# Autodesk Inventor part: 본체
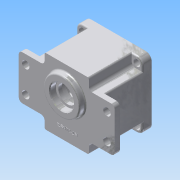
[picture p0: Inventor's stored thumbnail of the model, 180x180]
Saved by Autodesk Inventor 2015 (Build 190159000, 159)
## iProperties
Created: 2015-06
Part Number: 본체
Material: 알루미늄 6061
Document SubType Name: Modeling
Designer: AMC
Density: 2.7 g/cm^3
Appearance: 알루미늄 - 평지
Mass: 682.745 g
Surface Area: 675.046 cm^2
Volume: 252.868 cm^3
Author: AMC
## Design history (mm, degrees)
sketch "스케치1"
  geometry: L1 (0, 0)-(90, 0); L2 (90, 0)-(90, 90); L3 (90, 90)-(0, 90); L4 (0, 90)-(0, 0)
  constraints: 8 end point, 2 parallel, 1 horizontal, 1 perpendicular
  dimensions: "d0" = 90 distance of L2.end L3.end; "d1" = 90 distance of L1.end L2.end
extrude "돌출1" new body sketch "스케치1" distance "d2" = 12; taper "d3" = 0 deg
sketch "스케치2"
  geometry: L1 (75, 75)-(15, 75); L2 (15, 75)-(15, 15); L3 (15, 15)-(75, 15); L4 (75, 15)-(75, 75); L5 (90, 90)-(0, 90) reference; L6 (90, 0)-(90, 90) reference; 5 further points
  constraints: 8 end point, 4 midpoint, 2 parallel, 1 horizontal, 1 horizontal alignment, 1 perpendicular, 1 vertical alignment
  dimensions: "d4" = 60 distance of L3.end L1.start; "d5" = 60 distance of L1.start L1.end
extrude "돌출2" join sketch "스케치2" distance "d6" = 58; taper "d7" = 0 deg
sketch "스케치3"
  geometry: L1 (75, 75)-(75, 15) reference; L2 (75, 15)-(15, 15) reference; L3 (15, 15)-(15, 75) reference; L4 (15, 75)-(75, 75) reference; L5 (75, 110)-(15, 110); L6 (15, 110)-(15, -20); L7 (15, -20)-(75, -20); L8 (75, -20)-(75, 110); L9 (90, 90)-(0, 90) reference; L10 (90, 0)-(90, 90) reference; 5 further points
  constraints: 8 end point, 4 midpoint, 2 parallel, 1 horizontal, 1 horizontal alignment, 1 perpendicular, 1 vertical alignment
  dimensions: "d8" = 130 distance of L7.end L5.start; "d9" = 60 distance of L5.start L5.end
extrude "돌출3" join sketch "스케치3" distance "d10" = 7; taper "d11" = 0 deg
fillet "모깎기1" dims "d12" = 5
fillet "모깎기2" dims "d13" = 8
fillet "모깎기3" dims "d14" = 5
sketch "스케치4"
  geometry: L1 (15, 20)-(15, 70) reference; L2 (20, 75)-(70, 75) reference; L3 (75, 70)-(75, 20) reference; L4 (70, 15)-(20, 15) reference; L5 (8, 90)-(82, 90) reference; L6 (90, 82)-(90, 8) reference; L7 (82, 0)-(8, 0) reference; L8 (0, 8)-(0, 82) reference; C1 r 4.5 at (82, 82); C2 r 4.5 at (82, 8); C3 r 4.5 at (8, 8); C4 r 4.5 at (8, 82); A1 r 5 centre (20, 20) between (15, 20) and (20, 15) reference; A2 r 5 centre (20, 70) between (20, 75) and (15, 70) reference; A3 r 5 centre (70, 70) between (75, 70) and (70, 75) reference; A4 r 5 centre (70, 20) between (70, 15) and (75, 20) reference; A5 r 8 centre (8, 82) between (8, 90) and (0, 82) reference; A6 r 8 centre (82, 82) between (90, 82) and (82, 90) reference; A7 r 8 centre (82, 8) between (82, 0) and (90, 8) reference; A8 r 8 centre (8, 8) between (0, 8) and (8, 0) reference; 1 further point
  constraints: 4 centre point, 4 coincident
  dimensions: "d15" = 9 diameter of C1; "d16" = 9 diameter of C2; "d17" = 9 diameter of C3; "d18" = 9 diameter of C4
extrude "돌출4" cut sketch "스케치4" distance "d19" = 7; taper "d20" = 0 deg
sketch "스케치5"
  geometry: L1 (75, 105)-(75, -15) reference; L2 (70, -20)-(20, -20) reference; L3 (15, -15)-(15, 105) reference; L4 (20, 110)-(70, 110) reference; L5 (90, 75)-(0, 75); L6 (0, 75)-(0, 15); L7 (0, 15)-(90, 15); L8 (90, 15)-(90, 75); L9 (90, 8)-(90, 82) reference; A1 r 5 centre (70, -15) between (70, -20) and (75, -15) reference; A2 r 5 centre (20, -15) between (15, -15) and (20, -20) reference; A3 r 5 centre (20, 105) between (20, 110) and (15, 105) reference; A4 r 5 centre (70, 105) between (75, 105) and (70, 110) reference; 5 further points
  constraints: 8 end point, 4 midpoint, 2 parallel, 1 coincident, 1 horizontal, 1 perpendicular, 1 vertical alignment
  dimensions: "d21" = 60 distance of L7.end L5.start; "d22" = 90 distance of L6.end L7.end
extrude "돌출5" join sketch "스케치5" stored distance "d23" = 7; taper "d24" = 0 deg
sketch "스케치6"
  geometry: L1 (0, 8)-(0, 15) reference; L2 (0, 15)-(0, 75) reference; L3 (0, 75)-(0, 82) reference; L4 (8, 90)-(82, 90) reference; L5 (90, 82)-(90, 75) reference; L6 (90, 75)-(90, 15) reference; L7 (90, 15)-(90, 8) reference; L8 (82, 0)-(8, 0) reference; L9 (90, 15)-(0, 15) reference; L10 (0, 75)-(90, 75) reference; L11 (75, 90)-(15, 90); L12 (15, 90)-(15, 0); L13 (15, 0)-(75, 0); L14 (75, 0)-(75, 90); C1 r 4.5 at (8, 8) reference; C2 r 4.5 at (82, 82) reference; C3 r 4.5 at (82, 8) reference; C4 r 4.5 at (8, 82) reference; A1 r 8 centre (8, 82) between (8, 90) and (0, 82) reference; A2 r 8 centre (82, 82) between (90, 82) and (82, 90) reference; A3 r 8 centre (82, 8) between (82, 0) and (90, 8) reference; A4 r 8 centre (8, 8) between (0, 8) and (8, 0) reference; 5 further points
  constraints: 8 end point, 4 midpoint, 2 parallel, 1 coincident, 1 horizontal, 1 horizontal alignment, 1 perpendicular
  dimensions: "d25" = 90 distance of L13.end L11.start; "d26" = 60 distance between parallel lines of L12 L14
extrude "돌출6" join sketch "스케치6" stored distance "d27" = 7; taper "d28" = 0 deg
fillet "모깎기4" dims "d29" = 5
sketch "스케치7"
  geometry: L1 (75, 10)-(75, -15) reference; L2 (70, -20)-(20, -20) reference; L3 (15, -15)-(15, 10) reference; L4 (10, 15)-(0, 15) reference; L5 (0, 15)-(0, 75) reference; L6 (0, 75)-(10, 75) reference; L7 (15, 80)-(15, 105) reference; L8 (20, 110)-(70, 110) reference; L9 (75, 105)-(75, 80) reference; L10 (80, 75)-(90, 75) reference; L11 (90, 75)-(90, 15) reference; L12 (90, 15)-(80, 15) reference; C1 r 5.072 at (62.5, 100.571); C2 r 5.147 at (62.5, -9.429); A1 r 5 centre (80, 10) between (80, 15) and (75, 10) reference; A2 r 5 centre (70, -15) between (70, -20) and (75, -15) reference; A3 r 5 centre (20, -15) between (15, -15) and (20, -20) reference; A4 r 5 centre (10, 10) between (15, 10) and (10, 15) reference; A5 r 5 centre (10, 80) between (10, 75) and (15, 80) reference; A6 r 5 centre (20, 105) between (20, 110) and (15, 105) reference; A7 r 5 centre (70, 105) between (75, 105) and (70, 110) reference; A8 r 5 centre (80, 80) between (75, 80) and (80, 75) reference; 1 further point
  constraints: 2 centre point
  dimensions: "d30" = 110 distance of C2.centre C1.centre; "d31" = 12.5 distance from line of C1.centre L9
extrude "돌출7" cut sketch "스케치7" distance "d32" = 7; taper "d33" = 0 deg
node "작업 평면1"
fillet "모깎기5" dims "d34" = 2
node "작업 평면2"
sketch "스케치9"
  geometry: L1 (-8, 70)-(82, 70) reference; L2 (82, 70)-(82, 0) reference; L3 (82, 0)-(-8, 0) reference; L4 (-8, 0)-(-8, 70) reference; L5 (37, 88.411)-(37, -11); L6 (77, 0)-(77, 9); L7 (77, 9)-(76, 9); L8 (76, 9)-(76, 61); L9 (76, 61)-(37, 61); L10 (77, 0)-(37, 0); L11 (37, 61)-(37, 0)
  constraints: 14 end point, 3 vertical, 2 collinear, 2 perpendicular, 1 midpoint, 1 point on line
  dimensions: "d39" = 9 distance of L6.start L6.end; "d40" = 1 distance of L6.end L7.end; "d42" = 52 distance of L7.end L8.end
revolve "회전1" sketch "스케치9" stored, may be unused: angle "d46" = 90 deg
sketch "스케치11"
  geometry: L1 (-30, 35)-(-30, 43) reference; L2 (-28, 45)-(28, 45) reference; L3 (30, 43)-(30, 35) reference; L4 (35, 30)-(43, 30) reference; L5 (45, 28)-(45, -28) reference; L6 (43, -30)-(35, -30) reference; L7 (30, -35)-(30, -43) reference; L8 (28, -45)-(-28, -45) reference; L9 (-30, -43)-(-30, -35) reference; L10 (-35, -30)-(-43, -30) reference; L11 (-45, -28)-(-45, 28) reference; L12 (-43, 30)-(-35, 30) reference; C1 r 39 at (0, 0) reference; C2 r 20.5 at (-11, 0); C3 r 14 at (20, 0); A1 r 5 centre (-35, 35) between (-35, 30) and (-30, 35) reference; A2 r 2 centre (-28, 43) between (-28, 45) and (-30, 43) reference; A3 r 2 centre (28, 43) between (30, 43) and (28, 45) reference; A4 r 5 centre (35, 35) between (30, 35) and (35, 30) reference; A5 r 2 centre (43, 28) between (45, 28) and (43, 30) reference; A6 r 2 centre (43, -28) between (43, -30) and (45, -28) reference; A7 r 5 centre (35, -35) between (35, -30) and (30, -35) reference; A8 r 2 centre (28, -43) between (28, -45) and (30, -43) reference; A9 r 2 centre (-28, -43) between (-30, -43) and (-28, -45) reference; A10 r 5 centre (-35, -35) between (-30, -35) and (-35, -30) reference; A11 r 2 centre (-43, -28) between (-45, -28) and (-43, -30) reference; A12 r 2 centre (-43, 28) between (-43, 30) and (-45, 28) reference; 1 further point
  constraints: 2 centre point
  dimensions: "d54" = 41 diameter of C2; "d55" = 11 distance of C1.centre C2.centre; "d56" = 28 diameter of C3; "d57" = 31 distance of C3.centre C2.centre
extrude "돌출9" join sketch "스케치11" distance "d58" = 7; taper "d59" = 0 deg
sketch "스케치12"
  geometry: L1 (-30, 35)-(-30, 43) reference; L2 (-28, 45)-(28, 45) reference; L3 (30, 43)-(30, 35) reference; L4 (35, 30)-(43, 30) reference; L5 (45, 28)-(45, -28) reference; L6 (43, -30)-(35, -30) reference; L7 (30, -35)-(30, -43) reference; L8 (28, -45)-(-28, -45) reference; L9 (-30, -43)-(-30, -35) reference; L10 (-35, -30)-(-43, -30) reference; L11 (-45, -28)-(-45, 28) reference; L12 (-43, 30)-(-35, 30) reference; C1 r 39 at (0, 0) reference; C2 r 17.5 at (-11, 0); A1 r 20.5 centre (-11, 0) between (6.5, 10.677) and (6.5, -10.677) reference; A2 r 12.5 centre (0, 0) between (9.006, 8.668) and (6.5, 10.677) reference; A3 r 14 centre (20, 0) between (9.006, -8.668) and (9.006, 8.668) reference; A4 r 12.5 centre (0, 0) between (6.5, -10.677) and (9.006, -8.668) reference; A5 r 5 centre (-35, 35) between (-35, 30) and (-30, 35) reference; A6 r 2 centre (-28, 43) between (-28, 45) and (-30, 43) reference; A7 r 2 centre (28, 43) between (30, 43) and (28, 45) reference; A8 r 5 centre (35, 35) between (30, 35) and (35, 30) reference; A9 r 2 centre (43, 28) between (45, 28) and (43, 30) reference; A10 r 2 centre (43, -28) between (43, -30) and (45, -28) reference; A11 r 5 centre (35, -35) between (35, -30) and (30, -35) reference; A12 r 2 centre (28, -43) between (28, -45) and (30, -43) reference; A13 r 2 centre (-28, -43) between (-30, -43) and (-28, -45) reference; A14 r 5 centre (-35, -35) between (-30, -35) and (-35, -30) reference; A15 r 2 centre (-43, -28) between (-45, -28) and (-43, -30) reference; A16 r 2 centre (-43, 28) between (-43, 30) and (-45, 28) reference; 1 further point
  constraints: 1 centre point, 1 coincident
  dimensions: "d60" = 35 diameter of C2
extrude "돌출10" cut sketch "스케치12" distance "d61" = 10; taper "d62" = 0 deg
node "작업 평면3"
sketch "스케치13"
  geometry: L1 (90, 17)-(90, 73) reference; L2 (20, 110)-(70, 110) reference; L3 (45, 110)-(45, -25.853); C1 r 25 at (56, 45); 2 further points
  constraints: 2 end point, 2 midpoint, 1 centre point, 1 horizontal alignment, 1 vertical
  dimensions: "d63" = 50 diameter of C1; "d65" = 11 distance from line of L3 C1.centre
extrude "돌출11" join sketch "스케치13" distance "d66" = 7; taper "d67" = 0 deg
hole "구멍2" diameter "d70" = 25; stored, may be unused: countersink angle "d74" = 90 deg, drill point angle "d76" = 118 deg; dims "d68" = 10, "d69" = 10, "d71" = 6, "d72" = 32, "d73" = 8, "d75" = 8
sketch "스케치14"
  geometry: L1 (-30, 35)-(-30, 43) reference; L2 (-28, 45)-(28, 45) reference; L3 (30, 43)-(30, 35) reference; L4 (35, 30)-(43, 30) reference; L5 (45, 28)-(45, -28) reference; L6 (43, -30)-(35, -30) reference; L7 (30, -35)-(30, -43) reference; L8 (28, -45)-(-28, -45) reference; L9 (-30, -43)-(-30, -35) reference; L10 (-35, -30)-(-43, -30) reference; L11 (-45, -28)-(-45, 28) reference; L12 (-43, 30)-(-35, 30) reference; C1 r 12.5 at (-11, 0) reference; C2 r 39 at (0, 0) reference; C3 r 20.5 at (-11, 0); C4 r 14 at (20, 0); A1 r 5 centre (-35, 35) between (-35, 30) and (-30, 35) reference; A2 r 2 centre (-28, 43) between (-28, 45) and (-30, 43) reference; A3 r 2 centre (28, 43) between (30, 43) and (28, 45) reference; A4 r 5 centre (35, 35) between (30, 35) and (35, 30) reference; A5 r 2 centre (43, 28) between (45, 28) and (43, 30) reference; A6 r 2 centre (43, -28) between (43, -30) and (45, -28) reference; A7 r 5 centre (35, -35) between (35, -30) and (30, -35) reference; A8 r 2 centre (28, -43) between (28, -45) and (30, -43) reference; A9 r 2 centre (-28, -43) between (-30, -43) and (-28, -45) reference; A10 r 5 centre (-35, -35) between (-30, -35) and (-35, -30) reference; A11 r 2 centre (-43, -28) between (-45, -28) and (-43, -30) reference; A12 r 2 centre (-43, 28) between (-43, 30) and (-45, 28) reference; 1 further point
  constraints: 2 centre point, 1 coincident
  dimensions: "d77" = 41 diameter of C3; "d78" = 31 distance of C4.centre C1.centre; "d79" = 28 diameter of C4
extrude "돌출12" join sketch "스케치14" distance "d80" = 7; taper "d81" = 0 deg
sketch "스케치15"
  geometry: L1 (-30, 35)-(-30, 43) reference; L2 (-28, 45)-(28, 45) reference; L3 (30, 43)-(30, 35) reference; L4 (35, 30)-(43, 30) reference; L5 (45, 28)-(45, -28) reference; L6 (43, -30)-(35, -30) reference; L7 (30, -35)-(30, -43) reference; L8 (28, -45)-(-28, -45) reference; L9 (-30, -43)-(-30, -35) reference; L10 (-35, -30)-(-43, -30) reference; L11 (-45, -28)-(-45, 28) reference; L12 (-43, 30)-(-35, 30) reference; C1 r 12.5 at (-11, 0) reference; C2 r 39 at (0, 0) reference; C3 r 17.5 at (-11, 0); A1 r 20.5 centre (-11, 0) between (8.117, 7.402) and (8.117, -7.402) reference; A2 r 14 centre (20, 0) between (8.117, -7.402) and (8.117, 7.402) reference; A3 r 5 centre (-35, 35) between (-35, 30) and (-30, 35) reference; A4 r 2 centre (-28, 43) between (-28, 45) and (-30, 43) reference; A5 r 2 centre (28, 43) between (30, 43) and (28, 45) reference; A6 r 5 centre (35, 35) between (30, 35) and (35, 30) reference; A7 r 2 centre (43, 28) between (45, 28) and (43, 30) reference; A8 r 2 centre (43, -28) between (43, -30) and (45, -28) reference; A9 r 5 centre (35, -35) between (35, -30) and (30, -35) reference; A10 r 2 centre (28, -43) between (28, -45) and (30, -43) reference; A11 r 2 centre (-28, -43) between (-30, -43) and (-28, -45) reference; A12 r 5 centre (-35, -35) between (-30, -35) and (-35, -30) reference; A13 r 2 centre (-43, -28) between (-45, -28) and (-43, -30) reference; A14 r 2 centre (-43, 28) between (-43, 30) and (-45, 28) reference; 1 further point
  constraints: 1 centre point, 1 coincident
  dimensions: "d82" = 35 diameter of C3
extrude "돌출13" cut sketch "스케치15" distance "d83" = 10; taper "d84" = 0 deg
sketch "스케치16"
  geometry: L1 (-30, 35)-(-30, 43) reference; L2 (-28, 45)-(28, 45) reference; L3 (30, 43)-(30, 35) reference; L4 (35, 30)-(43, 30) reference; L5 (45, 28)-(45, -28) reference; L6 (43, -30)-(35, -30) reference; L7 (30, -35)-(30, -43) reference; L8 (28, -45)-(-28, -45) reference; L9 (-30, -43)-(-30, -35) reference; L10 (-35, -30)-(-43, -30) reference; L11 (-45, -28)-(-45, 28) reference; L12 (-43, 30)-(-35, 30) reference; C1 r 17.5 at (-11, 0) reference; C2 r 39 at (0, 0) reference; C3 r 11 at (20, 0); A1 r 20.5 centre (-11, 0) between (8.117, 7.402) and (8.117, -7.402) reference; A2 r 14 centre (20, 0) between (8.117, -7.402) and (8.117, 7.402) reference; A3 r 5 centre (-35, 35) between (-35, 30) and (-30, 35) reference; A4 r 2 centre (-28, 43) between (-28, 45) and (-30, 43) reference; A5 r 2 centre (28, 43) between (30, 43) and (28, 45) reference; A6 r 5 centre (35, 35) between (30, 35) and (35, 30) reference; A7 r 2 centre (43, 28) between (45, 28) and (43, 30) reference; A8 r 2 centre (43, -28) between (43, -30) and (45, -28) reference; A9 r 5 centre (35, -35) between (35, -30) and (30, -35) reference; A10 r 2 centre (28, -43) between (28, -45) and (30, -43) reference; A11 r 2 centre (-28, -43) between (-30, -43) and (-28, -45) reference; A12 r 5 centre (-35, -35) between (-30, -35) and (-35, -30) reference; A13 r 2 centre (-43, -28) between (-45, -28) and (-43, -30) reference; A14 r 2 centre (-43, 28) between (-43, 30) and (-45, 28) reference; 1 further point
  constraints: 1 centre point, 1 coincident
  dimensions: "d85" = 22 diameter of C3
extrude "돌출14" cut sketch "스케치16" distance "d86" = 7; taper "d87" = 0 deg
sketch "스케치17"
  geometry: L1 (-50, 35)-(-50, 43) reference; L2 (-48, 45)-(8, 45) reference; L3 (10, 43)-(10, 35) reference; L4 (15, 30)-(23, 30) reference; L5 (25, 28)-(25, -28) reference; L6 (23, -30)-(15, -30) reference; L7 (10, -35)-(10, -43) reference; L8 (8, -45)-(-48, -45) reference; L9 (-50, -43)-(-50, -35) reference; L10 (-55, -30)-(-63, -30) reference; L11 (-65, -28)-(-65, 28) reference; L12 (-63, 30)-(-55, 30) reference; C1 r 11 at (0, 0) reference; C2 r 17.5 at (-31, 0) reference; C3 r 39 at (-20, 0) reference; C4 r 9.5 at (0, 0); A1 r 20.5 centre (-31, 0) between (-11.883, 7.402) and (-11.883, -7.402) reference; A2 r 14 centre (0, 0) between (-11.883, -7.402) and (-11.883, 7.402) reference; A3 r 5 centre (-55, 35) between (-55, 30) and (-50, 35) reference; A4 r 2 centre (-48, 43) between (-48, 45) and (-50, 43) reference; A5 r 2 centre (8, 43) between (10, 43) and (8, 45) reference; A6 r 5 centre (15, 35) between (10, 35) and (15, 30) reference; A7 r 2 centre (23, 28) between (25, 28) and (23, 30) reference; A8 r 2 centre (23, -28) between (23, -30) and (25, -28) reference; A9 r 5 centre (15, -35) between (15, -30) and (10, -35) reference; A10 r 2 centre (8, -43) between (8, -45) and (10, -43) reference; A11 r 2 centre (-48, -43) between (-50, -43) and (-48, -45) reference; A12 r 5 centre (-55, -35) between (-50, -35) and (-55, -30) reference; A13 r 2 centre (-63, -28) between (-65, -28) and (-63, -30) reference; A14 r 2 centre (-63, 28) between (-63, 30) and (-65, 28) reference; 1 further point
  constraints: 1 centre point, 1 coincident
  dimensions: "d88" = 19 diameter of C4
extrude "돌출15" cut sketch "스케치17" distance "d89" = 1; taper "d90" = 0 deg
sketch "스케치18" dims "d91" = 70
  geometry: L1 (-30, 35)-(-30, 43) reference; L2 (-28, 45)-(28, 45) reference; L3 (30, 43)-(30, 35) reference; L4 (35, 30)-(43, 30) reference; L5 (45, 28)-(45, -28) reference; L6 (43, -30)-(35, -30) reference; L7 (30, -35)-(30, -43) reference; L8 (28, -45)-(-28, -45) reference; L9 (-30, -43)-(-30, -35) reference; L10 (-35, -30)-(-43, -30) reference; L11 (-45, -28)-(-45, 28) reference; L12 (-43, 30)-(-35, 30) reference; L13 (0, 0)-(38.536, -38.536); L14 (0, 0)-(54.497, 0); L15 (26.331, -21.075)-(35.701, -25.112); L16 (23.543, -36.581)-(20.865, -25.705); L17 (19.284, -19.284)-(19.237, -19.093); C1 r 9.5 at (20, 0) reference; C2 r 11 at (20, 0) reference; C3 r 17.5 at (-11, 0) reference; C4 r 39 at (0, 0) reference; A1 r 20.5 centre (-11, 0) between (8.117, 7.402) and (8.117, -7.402) reference; A2 r 14 centre (20, 0) between (8.117, -7.402) and (8.117, 7.402) reference; A3 r 5 centre (-35, 35) between (-35, 30) and (-30, 35) reference; A4 r 2 centre (-28, 43) between (-28, 45) and (-30, 43) reference; A5 r 2 centre (28, 43) between (30, 43) and (28, 45) reference; A6 r 5 centre (35, 35) between (30, 35) and (35, 30) reference; A7 r 2 centre (43, 28) between (45, 28) and (43, 30) reference; A8 r 2 centre (43, -28) between (43, -30) and (45, -28) reference; A9 r 5 centre (35, -35) between (35, -30) and (30, -35) reference; A10 r 2 centre (28, -43) between (28, -45) and (30, -43) reference; A11 r 2 centre (-28, -43) between (-30, -43) and (-28, -45) reference; A12 r 5 centre (-35, -35) between (-30, -35) and (-35, -30) reference; A13 r 2 centre (-43, -28) between (-45, -28) and (-43, -30) reference; A14 r 2 centre (-43, 28) between (-43, 30) and (-45, 28) reference; A15 r 4 centre (24.749, -24.749) between (20.865, -25.705) and (26.331, -21.075); A16 r 39 centre (0, 0) between (22.397, -31.928) and (39, 0); 1 further point
  constraints: 10 end point, 5 point on circle, 4 point on line, 3 tangent, 2 centre point, 2 coincident, 1 equal length, 1 horizontal, 3 other
  dimensions: "d92" = 45 deg angle of L13 L14; "d93" = 8 diameter of A15
extrude "돌출16" join sketch "스케치18" distance "d94" = 52; taper "d95" = 0 deg
sketch "스케치19"
  geometry: L1 (-30, 35)-(-30, 43) reference; L2 (-28, 45)-(28, 45) reference; L3 (30, 43)-(30, 35) reference; L4 (35, 30)-(43, 30) reference; L5 (45, 28)-(45, -28) reference; L6 (43, -30)-(35, -30) reference; L7 (30, -35)-(30, -43) reference; L8 (28, -45)-(-28, -45) reference; L9 (-30, -43)-(-30, -35) reference; L10 (-35, -30)-(-43, -30) reference; L11 (-45, -28)-(-45, 28) reference; L12 (-43, 30)-(-35, 30) reference; L13 (23.419, -31.186)-(21.148, -26.49); L14 (25.68, -20.859)-(31.954, -22.36); C1 r 9.5 at (20, 0) reference; C2 r 11 at (20, 0) reference; C3 r 17.5 at (-11, 0) reference; A1 r 4 centre (24.749, -24.749) between (27.577, -27.577) and (21.148, -26.49) reference; A2 r 39 centre (0, 0) between (27.577, -27.577) and (31.954, -22.36) reference; A3 r 20.5 centre (-11, 0) between (8.117, 7.402) and (8.117, -7.402) reference; A4 r 14 centre (20, 0) between (8.117, -7.402) and (8.117, 7.402) reference; A5 r 5 centre (-35, 35) between (-35, 30) and (-30, 35) reference; A6 r 2 centre (-28, 43) between (-28, 45) and (-30, 43) reference; A7 r 2 centre (28, 43) between (30, 43) and (28, 45) reference; A8 r 5 centre (35, 35) between (30, 35) and (35, 30) reference; A9 r 2 centre (43, 28) between (45, 28) and (43, 30) reference; A10 r 2 centre (43, -28) between (43, -30) and (45, -28) reference; A11 r 5 centre (35, -35) between (35, -30) and (30, -35) reference; A12 r 2 centre (28, -43) between (28, -45) and (30, -43) reference; A13 r 2 centre (-28, -43) between (-30, -43) and (-28, -45) reference; A14 r 5 centre (-35, -35) between (-30, -35) and (-35, -30) reference; A15 r 2 centre (-43, -28) between (-45, -28) and (-43, -30) reference; A16 r 2 centre (-43, 28) between (-43, 30) and (-45, 28) reference; A17 r 39 centre (0, 0) between (23.419, -31.186) and (31.954, -22.36); 1 further point
  constraints: 7 point on circle, 4 end point, 2 tangent, 1 centre point
extrude "돌출17" join sketch "스케치19" distance "d96" = 52; taper "d97" = 0 deg
fillet "모깎기6" dims "d98" = 2
sketch "스케치20"
  geometry: L1 (22.686, -29.671)-(21.148, -26.49) reference; L2 (25.68, -20.859)-(30.604, -22.037) reference; L3 (29.671, 22.686)-(26.49, 21.148) reference; L4 (20.859, 25.68)-(22.037, 30.604) reference; L5 (-22.686, 29.671)-(-21.148, 26.49) reference; L6 (-25.68, 20.859)-(-30.604, 22.037) reference; L7 (-29.671, -22.686)-(-26.49, -21.148) reference; L8 (-20.859, -25.68)-(-22.037, -30.604) reference; L9 (-45, -37)-(-45, 37) reference; L10 (-37, 45)-(37, 45) reference; L11 (45, 37)-(45, -37) reference; L12 (37, -45)-(-37, -45) reference; C1 r 40 at (0, 0) reference; C2 r 4.5 at (37, -37) reference; C3 r 4.5 at (-37, 37) reference; C4 r 4.5 at (-37, -37) reference; C5 r 4.5 at (37, 37) reference; A1 r 2 centre (-20.092, -31.07) between (-22.037, -30.604) and (-21.178, -32.749) reference; A2 r 39 centre (0, 0) between (-21.178, -32.749) and (22.015, -32.192) reference; A3 r 2 centre (20.886, -30.542) between (22.015, -32.192) and (22.686, -29.671) reference; A4 r 4 centre (24.749, -24.749) between (25.68, -20.859) and (21.148, -26.49) reference; A5 r 2 centre (31.07, -20.092) between (30.604, -22.037) and (32.749, -21.178) reference; A6 r 39 centre (0, 0) between (32.749, -21.178) and (32.192, 22.015) reference; A7 r 2 centre (30.542, 20.886) between (32.192, 22.015) and (29.671, 22.686) reference; A8 r 4 centre (24.749, 24.749) between (20.859, 25.68) and (26.49, 21.148) reference; A9 r 2 centre (20.092, 31.07) between (22.037, 30.604) and (21.178, 32.749) reference; A10 r 39 centre (0, 0) between (21.178, 32.749) and (-22.015, 32.192) reference; A11 r 2 centre (-20.886, 30.542) between (-22.015, 32.192) and (-22.686, 29.671) reference; A12 r 4 centre (-24.749, 24.749) between (-25.68, 20.859) and (-21.148, 26.49) reference; A13 r 2 centre (-31.07, 20.092) between (-30.604, 22.037) and (-32.749, 21.178) reference; A14 r 39 centre (0, 0) between (-32.749, 21.178) and (-32.192, -22.015) reference; A15 r 2 centre (-30.542, -20.886) between (-32.192, -22.015) and (-29.671, -22.686) reference; A16 r 4 centre (-24.749, -24.749) between (-20.859, -25.68) and (-26.49, -21.148) reference; A17 r 8 centre (-37, 37) between (-37, 45) and (-45, 37) reference; A18 r 8 centre (37, 37) between (45, 37) and (37, 45) reference; A19 r 8 centre (37, -37) between (37, -45) and (45, -37) reference; A20 r 8 centre (-37, -37) between (-45, -37) and (-37, -45) reference; 5 further points
  constraints: 4 coincident
hole "구멍3" sketch "스케치20" at (24.749, 24.749), (-24.749, 24.749), (-24.749, -24.749), (24.749, -24.749) diameter "d102" = 3.242; stored, may be unused: countersink angle "d106" = 90 deg, drill point angle "d108" = 118 deg; dims "d103" = 12, "d104" = 22, "d105" = 7, "d107" = 15
fillet "모깎기7" dims "d109" = 2
fillet "모깎기8" dims "d110" = 0.3
fillet "모깎기9" dims "d111" = 2
fillet "모깎기10" dims "d112" = 0.3
chamfer "모따기1" distance "d113" = 1; stored, may be unused: second distance "d114" = 2, angle "d115" = 45 deg
fillet "모깎기11" dims "d116" = 2
node "작업 평면4"
sketch "스케치21"
  geometry: L1 (0, 73)-(0, 17) reference; 2 further points
  constraints: 1 other
  dimensions: "d118" = 15 distance from line of L1 point (15, 43.868)
feature "엠보싱1" sketch "스케치21" dims "d119" = 0.5, "d120" = 0
sketch "스케치22"
  geometry: L1 (-8, 0)-(-82, 0) reference; L2 (-90, 8)-(-90, 82) reference; L3 (-82, 90)-(-8, 90) reference; L4 (0, 82)-(0, 8) reference; C1 r 40 at (-45, 45) reference; C2 r 4.5 at (-82, 8) reference; C3 r 4.5 at (-82, 8); C4 r 4.5 at (-82, 82); C5 r 4.5 at (-8, 82) reference; C6 r 4.5 at (-8, 82); C7 r 4.5 at (-8, 8) reference; C8 r 4.5 at (-8, 8); A1 r 8 centre (-82, 8) between (-90, 8) and (-82, 0) reference; A2 r 8 centre (-82, 82) between (-82, 90) and (-90, 82) reference; A3 r 8 centre (-8, 82) between (0, 82) and (-8, 90) reference; A4 r 8 centre (-8, 8) between (-8, 0) and (0, 8) reference; 1 further point
  constraints: 4 centre point, 4 coincident
extrude "돌출18" cut sketch "스케치22" distance "d121" = 10; taper "d122" = 0 deg
node "솔리드1"
mirror "대칭1"
pattern_circular "원형 패턴1" dims "d100" = 360 deg
node "절단 모서리 투영1"
node "절단 모서리 투영2"
node "절단 모서리 투영3"
node "절단 모서리 투영4"
node "절단 모서리 투영5"
node "절단 모서리 투영6"
node "절단 모서리 투영8"
node "절단 모서리 투영9"
node "절단 모서리 투영10"
node "절단 모서리 투영11"
node "절단 모서리 투영12"
node "절단 모서리 투영13"
node "절단 모서리 투영14"
node "절단 모서리 투영15"
node "절단 모서리 투영16"
node "절단 모서리 투영17"
